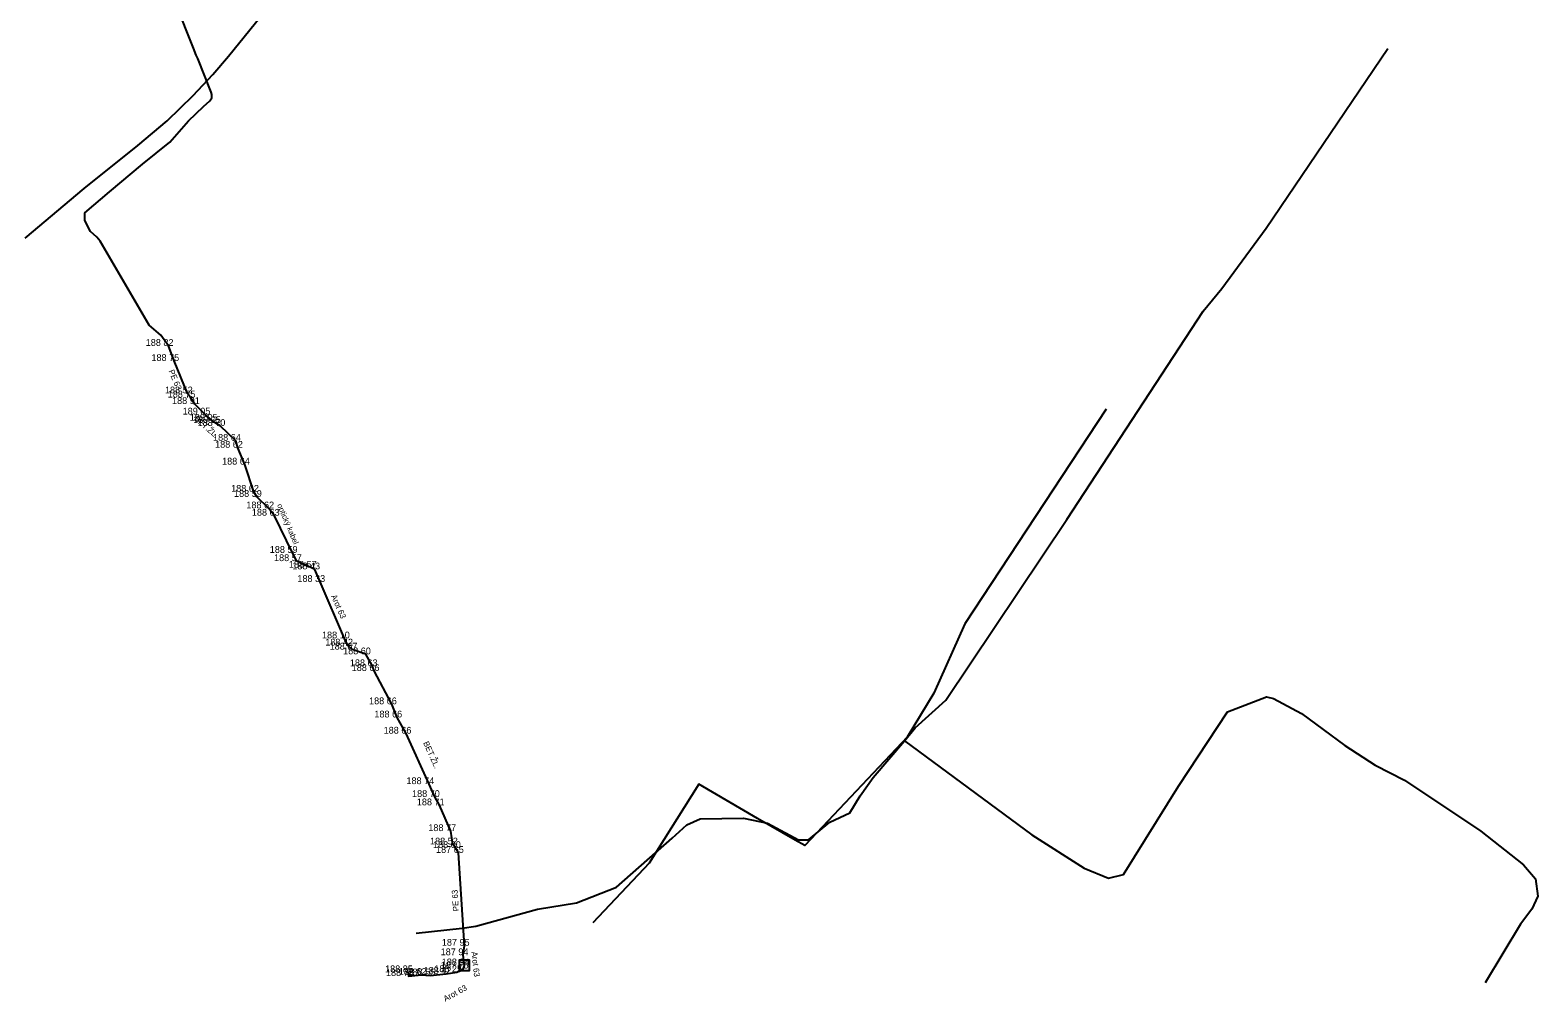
# Model space of a CAD drawing. Extents: x -539701 to -539089, y -1156443 to -1155859.
# Drawn here: x -539412.2 to -539245.6, y -1156060.3 to -1155952.9 of the extents above; entities that cross this region are included whole.
import ezdxf

# ---------------------------------------------------------------- set-up
doc = ezdxf.new("R2010")
doc.units = 0
for name, color, linetype in [('Vrstva 1', 7, 'Continuous'), ('Vrstva 19', 7, 'Continuous'), ('Vrstva 25', 7, 'Continuous'), ('Vrstva 3', 7, 'Continuous'), ('Vrstva 31', 7, 'Continuous'), ('Vrstva 38', 7, 'Continuous'), ('Vrstva 45', 7, 'Continuous'), ('Vrstva 49', 7, 'Continuous')]:
    doc.layers.add(name, color=color, linetype=linetype)

msp = doc.modelspace()

# ---------------------------------------------------------------- linework, layer by layer
at = {"layer": 'Vrstva 1'}
for p, q in [((-539396.9, -1155987.82), (-539396.9, -1155987.82)), ((-539396.27, -1155989.49), (-539396.27, -1155989.49)), ((-539394.77, -1155993.07), (-539394.77, -1155993.07)), ((-539394.47, -1155993.53), (-539394.47, -1155993.53)), ((-539393.99, -1155994.25), (-539393.99, -1155994.25)), ((-539392.82, -1155995.41), (-539392.82, -1155995.41)), ((-539392.03, -1155996.1), (-539392.03, -1155996.1)), ((-539391.66, -1155996.35), (-539391.66, -1155996.35)), ((-539391.17, -1155996.67), (-539391.17, -1155996.67)), ((-539389.46, -1155998.31), (-539389.46, -1155998.31)), ((-539389.23, -1155999.08), (-539389.23, -1155999.08)), ((-539388.46, -1156000.94), (-539388.46, -1156000.94)), ((-539387.46, -1156003.94), (-539387.46, -1156003.94)), ((-539387.14, -1156004.51), (-539387.14, -1156004.51)), ((-539385.78, -1156005.78), (-539385.78, -1156005.78)), ((-539385.17, -1156006.59), (-539385.17, -1156006.59)), ((-539383.19, -1156010.7), (-539383.19, -1156010.7)), ((-539382.72, -1156011.61), (-539382.72, -1156011.61)), ((-539381.08, -1156012.34), (-539381.08, -1156012.34)), ((-539380.7, -1156012.52), (-539380.7, -1156012.52)), ((-539380.14, -1156013.91), (-539380.14, -1156013.91)), ((-539377.42, -1156020.15), (-539377.42, -1156020.15)), ((-539377.06, -1156020.94), (-539377.06, -1156020.94)), ((-539376.58, -1156021.39), (-539376.58, -1156021.39)), ((-539375.09, -1156021.91), (-539375.09, -1156021.91)), ((-539374.34, -1156023.23), (-539374.34, -1156023.23)), ((-539374.14, -1156023.75), (-539374.14, -1156023.75)), ((-539372.22, -1156027.43), (-539372.22, -1156027.43)), ((-539371.63, -1156028.89), (-539371.63, -1156028.89)), ((-539370.61, -1156030.68), (-539370.61, -1156030.68)), ((-539368.09, -1156036.26), (-539368.09, -1156036.26)), ((-539367.47, -1156037.68), (-539367.47, -1156037.68)), ((-539366.94, -1156038.6), (-539366.94, -1156038.6)), ((-539365.67, -1156041.45), (-539365.67, -1156041.45)), ((-539365.48, -1156042.93), (-539365.48, -1156042.93)), ((-539365.15, -1156043.32), (-539365.15, -1156043.32)), ((-539364.82, -1156043.86), (-539364.82, -1156043.86)), ((-539364.18, -1156054.12), (-539364.18, -1156054.12)), ((-539364.31, -1156055.17), (-539364.31, -1156055.17)), ((-539370.45, -1156057.05), (-539370.45, -1156057.05)), ((-539370.35, -1156057.47), (-539370.35, -1156057.47)), ((-539368.93, -1156057.33), (-539368.93, -1156057.33)), ((-539367.98, -1156057.4), (-539367.98, -1156057.4)), ((-539366.19, -1156057.22), (-539366.19, -1156057.22)), ((-539365.02, -1156057.04), (-539365.02, -1156057.04)), ((-539364.29, -1156056.64), (-539364.29, -1156056.64)), ((-539364.19, -1156056.29), (-539364.19, -1156056.29))]:
    msp.add_line(p, q, dxfattribs=at)
at = {"layer": 'Vrstva 25'}
msp.add_line((-539394.77, -1155993.07), (-539396.27, -1155989.49), dxfattribs=at)
for points in [[(-539412.72, -1155975.91), (-539406.19, -1155970.41), (-539400.28, -1155965.66), (-539397.02, -1155962.93), (-539394.17, -1155960.14), (-539391.97, -1155957.84), (-539390.27, -1155955.81), (-539386.16, -1155950.77)], [(-539391.66, -1155996.35), (-539392.03, -1155996.1), (-539392.82, -1155995.41)], [(-539376.58, -1156021.39), (-539377.06, -1156020.94), (-539377.42, -1156020.15), (-539380.14, -1156013.91)], [(-539365.15, -1156043.32), (-539365.48, -1156042.93), (-539365.67, -1156041.45), (-539366.94, -1156038.6), (-539367.47, -1156037.68), (-539368.09, -1156036.26), (-539370.61, -1156030.68), (-539371.63, -1156028.89), (-539372.22, -1156027.43), (-539374.14, -1156023.75), (-539374.34, -1156023.23), (-539375.09, -1156021.91), (-539376.58, -1156021.39)], [(-539364.18, -1156054.12), (-539364.82, -1156043.86), (-539365.15, -1156043.32)], [(-539364.19, -1156056.29), (-539364.31, -1156055.17), (-539364.18, -1156054.12)], [(-539365.02, -1156057.04), (-539364.29, -1156056.64), (-539364.19, -1156056.29)]]:
    msp.add_lwpolyline(points, dxfattribs=at)
at = {"layer": 'Vrstva 31'}
msp.add_line((-539247.472, -1156051.739), (-539251.384, -1156058.208), dxfattribs=at)
for points in [[(-539315.546, -1156031.457), (-539314.39, -1156030.05), (-539310.97, -1156026.97), (-539297.62, -1156007), (-539282.54, -1155983.97), (-539280.5, -1155981.47), (-539275.59, -1155974.8), (-539262.138, -1155954.941)], [(-539293.255, -1155994.826), (-539308.905, -1156018.525), (-539312.31, -1156026.223), (-539315.252, -1156031.085), (-539325.91, -1156042.35)], [(-539315.546, -1156031.457), (-539306.12, -1156038.43), (-539301.48, -1156041.87), (-539295.7, -1156045.56), (-539293, -1156046.65), (-539291.37, -1156046.26), (-539285.269, -1156036.5), (-539279.877, -1156028.272), (-539275.536, -1156026.601), (-539274.762, -1156026.788), (-539271.698, -1156028.457), (-539266.914, -1156031.978), (-539263.541, -1156034.151), (-539260.312, -1156035.823), (-539251.865, -1156041.457), (-539247.145, -1156045.167), (-539245.82, -1156046.733), (-539245.569, -1156048.66), (-539246.22, -1156050.069), (-539247.472, -1156051.739)], [(-539369.51, -1156052.72), (-539364.44, -1156052.19), (-539362.94, -1156051.97), (-539356.1, -1156050.08), (-539351.81, -1156049.38), (-539347.39, -1156047.65), (-539341.22, -1156042.24), (-539339.62, -1156040.76), (-539338.14, -1156040.1), (-539333.36, -1156040.01), (-539330.69, -1156040.57), (-539327.25, -1156042.43), (-539326.18, -1156042.4), (-539323.8, -1156040.46), (-539321.61, -1156039.42), (-539320.45, -1156037.55), (-539319.01, -1156035.52), (-539315.546, -1156031.457)], [(-539327.65, -1156042.44), (-539331.8, -1156040.065), (-539338.273, -1156036.254), (-539343.761, -1156044.99), (-539350.008, -1156051.598)], [(-539325.91, -1156042.35), (-539326.578, -1156043.045), (-539327.65, -1156042.44)]]:
    msp.add_lwpolyline(points, dxfattribs=at)
at = {"layer": 'Vrstva 38'}
for points in [[(-539364.19, -1156056.29), (-539364.31, -1156055.17), (-539364.18, -1156054.12), (-539364.82, -1156043.86), (-539365.15, -1156043.32), (-539365.48, -1156042.93), (-539365.67, -1156041.45), (-539366.94, -1156038.6), (-539367.47, -1156037.68), (-539368.09, -1156036.26), (-539370.61, -1156030.68), (-539371.63, -1156028.89), (-539372.22, -1156027.43), (-539374.14, -1156023.75), (-539374.34, -1156023.23), (-539375.09, -1156021.91), (-539376.58, -1156021.39), (-539377.06, -1156020.94), (-539377.42, -1156020.15), (-539380.14, -1156013.91), (-539380.7, -1156012.52), (-539381.08, -1156012.34), (-539382.72, -1156011.61), (-539383.19, -1156010.7), (-539385.17, -1156006.59), (-539385.78, -1156005.78), (-539387.14, -1156004.51), (-539387.46, -1156003.94), (-539388.46, -1156000.94), (-539389.23, -1155999.08), (-539389.46, -1155998.31), (-539391.17, -1155996.67), (-539391.66, -1155996.35), (-539392.03, -1155996.1), (-539392.82, -1155995.41), (-539393.99, -1155994.25), (-539394.47, -1155993.53), (-539394.77, -1155993.07), (-539396.27, -1155989.49), (-539396.9, -1155987.82), (-539397.73, -1155986.64), (-539399.02, -1155985.54), (-539404.45, -1155976.26), (-539404.81, -1155975.79), (-539405.52, -1155975.17), (-539406.14, -1155973.96), (-539406.12, -1155973.11), (-539403.39, -1155970.78), (-539399.76, -1155967.75), (-539396.73, -1155965.32), (-539394.66, -1155962.96), (-539393.01, -1155961.37), (-539392.3, -1155960.73), (-539392.1, -1155960.41), (-539392.1, -1155960.04), (-539392.15, -1155959.79), (-539393.65, -1155956.07), (-539393.82, -1155955.68), (-539394.12, -1155954.9), (-539396.09, -1155950.03)], [(-539370.45, -1156057.05), (-539370.35, -1156057.47), (-539368.93, -1156057.33), (-539367.98, -1156057.4), (-539366.19, -1156057.22), (-539365.02, -1156057.04), (-539364.29, -1156056.64), (-539364.19, -1156056.29)]]:
    msp.add_lwpolyline(points, dxfattribs=at)
at = {"layer": 'Vrstva 45'}
msp.add_lwpolyline([(-539364.753, -1156056.851), (-539363.629, -1156056.851), (-539363.629, -1156055.727), (-539364.753, -1156055.727)], close=True, dxfattribs=at)

# ---------------------------------------------------------------- texts
at = {"layer": 'Vrstva 19'}
msp.add_text('optický kabel', height=0.6, rotation=292.83952, dxfattribs=at).set_placement((-539384.893, -1156005.405))
at = {"layer": 'Vrstva 3'}
for s, p in [('188 82 ', (-539399.4, -1155987.82)), ('188 75 ', (-539398.769, -1155989.49)), ('188 52 ', (-539397.27, -1155993.07)), ('188 75 ', (-539396.969, -1155993.53)), ('188 91 ', (-539396.49, -1155994.25)), ('189 05 ', (-539395.319, -1155995.41)), ('189 05 ', (-539394.529, -1155996.1)), ('189 05 ', (-539394.159, -1155996.35)), ('188 70 ', (-539393.67, -1155996.67)), ('188 64 ', (-539391.96, -1155998.31)), ('188 62 ', (-539391.73, -1155999.08)), ('188 64 ', (-539390.96, -1156000.94)), ('188 62 ', (-539389.96, -1156003.94)), ('188 59 ', (-539389.64, -1156004.51)), ('188 62 ', (-539388.28, -1156005.78)), ('188 63 ', (-539387.67, -1156006.59)), ('188 59 ', (-539385.69, -1156010.7)), ('188 57 ', (-539385.22, -1156011.61)), ('188 57 ', (-539383.58, -1156012.34)), ('188 43 ', (-539383.2, -1156012.52)), ('188 33 ', (-539382.64, -1156013.91)), ('188 10 ', (-539379.92, -1156020.15)), ('188 42 ', (-539379.56, -1156020.94)), ('188 67 ', (-539379.08, -1156021.39)), ('188 60 ', (-539377.59, -1156021.91)), ('188 63 ', (-539376.84, -1156023.23)), ('188 66 ', (-539376.64, -1156023.75)), ('188 66 ', (-539374.72, -1156027.43)), ('188 66 ', (-539374.13, -1156028.89)), ('188 66 ', (-539373.11, -1156030.68)), ('188 74 ', (-539370.59, -1156036.26)), ('188 70 ', (-539369.97, -1156037.68)), ('188 71 ', (-539369.44, -1156038.6)), ('188 77 ', (-539368.17, -1156041.45)), ('188 52 ', (-539367.98, -1156042.93)), ('188 00 ', (-539367.65, -1156043.32)), ('187 65 ', (-539367.319, -1156043.86)), ('187 95 ', (-539366.679, -1156054.12)), ('187 94 ', (-539366.81, -1156055.17)), ('187 75 ', (-539366.789, -1156056.64)), ('188 94 ', (-539366.69, -1156056.29)), ('188 85 ', (-539372.949, -1156057.05)), ('188 78 ', (-539372.85, -1156057.47)), ('188 62 ', (-539371.43, -1156057.33)), ('188 55 ', (-539370.479, -1156057.4)), ('188 42 ', (-539368.69, -1156057.22)), ('188 25 ', (-539367.519, -1156057.04))]:
    msp.add_text(s, height=0.75, dxfattribs=at).set_placement(p)
at = {"layer": 'Vrstva 49'}
for s, rotation, p in [('PE 63', 292.73341, (-539396.892, -1155990.605)), ('BET.ŽL.', 318.87528, (-539394.109, -1155995.962)), ('Arot 63', 293.55226, (-539378.94, -1156015.471)), ('BET.ŽL.', 294.31061, (-539368.76, -1156031.702)), ('PE 63', 93.56938, (-539364.795, -1156050.286)), ('Arot 63', 276.1155, (-539363.409, -1156054.801)), ('Arot 63', 28.72033, (-539366.287, -1156060.324))]:
    msp.add_text(s, height=0.65, rotation=rotation, dxfattribs=at).set_placement(p)

doc.saveas('drawing.dxf')
